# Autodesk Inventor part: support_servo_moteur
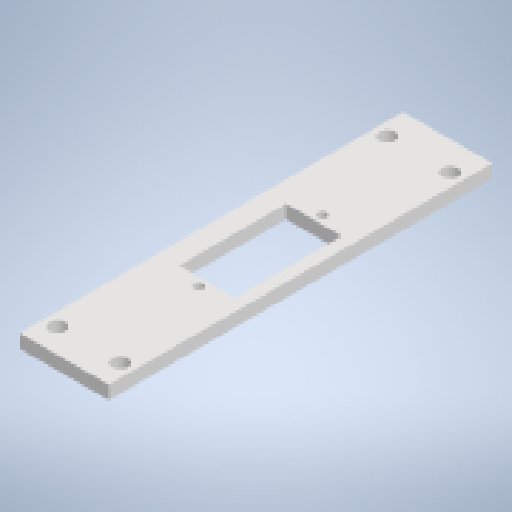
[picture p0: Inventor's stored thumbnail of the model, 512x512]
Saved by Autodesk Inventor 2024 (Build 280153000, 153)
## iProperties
Created: 2021-11
Part Number: support_servo_moteur
Material: Générique
Document SubType Name: Modeling
Designer: ropertth
Density: 1 g/cm^3
Appearance: Par défaut
Mass: 4.1257 g
Surface Area: 37.7511 cm^2
Volume: 4.1257 cm^3
Author: ropertth
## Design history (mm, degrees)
sketch "Esquisse1"
  geometry: L1 (0, 0)-(20, 0); L2 (20, 0)-(20, -86); L3 (20, -86)-(0, -86); L4 (0, -86)-(0, 0)
  constraints: 8 end point, 2 parallel, 1 horizontal, 1 perpendicular
  dimensions: "d0" = 86 distance of L1.end L2.end; "d1" = 20 distance of L1.start L1.end
extrude "Extrusion1" new body sketch "Esquisse1" distance "d2" = 3; taper "d3" = 0 deg
sketch "Esquisse2"
  geometry: L1 (-20, 0)-(0, 0) reference; L2 (0, 0)-(0, 86) reference; L3 (10.893, 42.5)-(-28.896, 42.5); 1 further point
  constraints: 2 end point, 1 horizontal
  dimensions: "d12" = 3 distance from line of L2 point (-3, 6); "d37" = 42.5 distance between parallel lines of L1 L3; "d39" = 36.5 distance from line of L3 point (-3, 6)
hole "Perçage1" sketch "Esquisse2" diameter "d4" = 3.5; stored, may be unused: countersink angle "d8" = 90 deg, drill point angle "d10" = 118 deg; dims "d5" = 6, "d6" = 4, "d7" = 2, "d9" = 8
pattern_linear "Réseau rectangulaire1" dims "d15" = 14, "d18" = 74
sketch "Esquisse3"
  geometry: L1 (-15.25, 31)-(-2.75, 31); L2 (-2.75, 31)-(-2.75, 55); L3 (-2.75, 55)-(-15.25, 55); L4 (-15.25, 55)-(-15.25, 31); L5 (0, 86)-(-20, 86) reference; L6 (-20, 86)-(-20, 0) reference; 1 further point
  constraints: 8 end point, 2 parallel, 1 horizontal, 1 perpendicular
  dimensions: "d19" = 24 distance of L3.end L1.start; "d20" = 12.5 distance of L2.end L3.end; "d21" = 31 distance between parallel lines of L5 L3; "d22" = 4.75 distance between parallel lines of L6 L4
extrude "Extrusion2" cut sketch "Esquisse3" extent not by distance; stored distance "d23" = 0; taper "d24" = 0 deg
sketch "Esquisse4"
  geometry: L1 (-2.75, 55)-(-2.75, 31) reference; L2 (-2.75, 31)-(-15.25, 31) reference; 2 further points
  dimensions: "d32" = 6.25 distance from line of L1 point (-9, 29.15); "d33" = 1.85 distance from line of L2 point (-9, 29.15)
hole "Perçage2" sketch "Esquisse4" diameter "d25" = 2; stored, may be unused: countersink angle "d29" = 90 deg, drill point angle "d31" = 118 deg; dims "d26" = 6, "d27" = 4, "d28" = 2, "d30" = 8
pattern_linear "Réseau rectangulaire2" dims "d36" = 27.7
node "Solide1"
